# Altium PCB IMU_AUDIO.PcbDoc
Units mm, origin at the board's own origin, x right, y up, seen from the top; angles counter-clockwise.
Board outline 152.4 x 101.6 mm, 2 copper layers (Top Layer, Bottom Layer); 89 components, 57 nets, 364 pads, 97 vias.
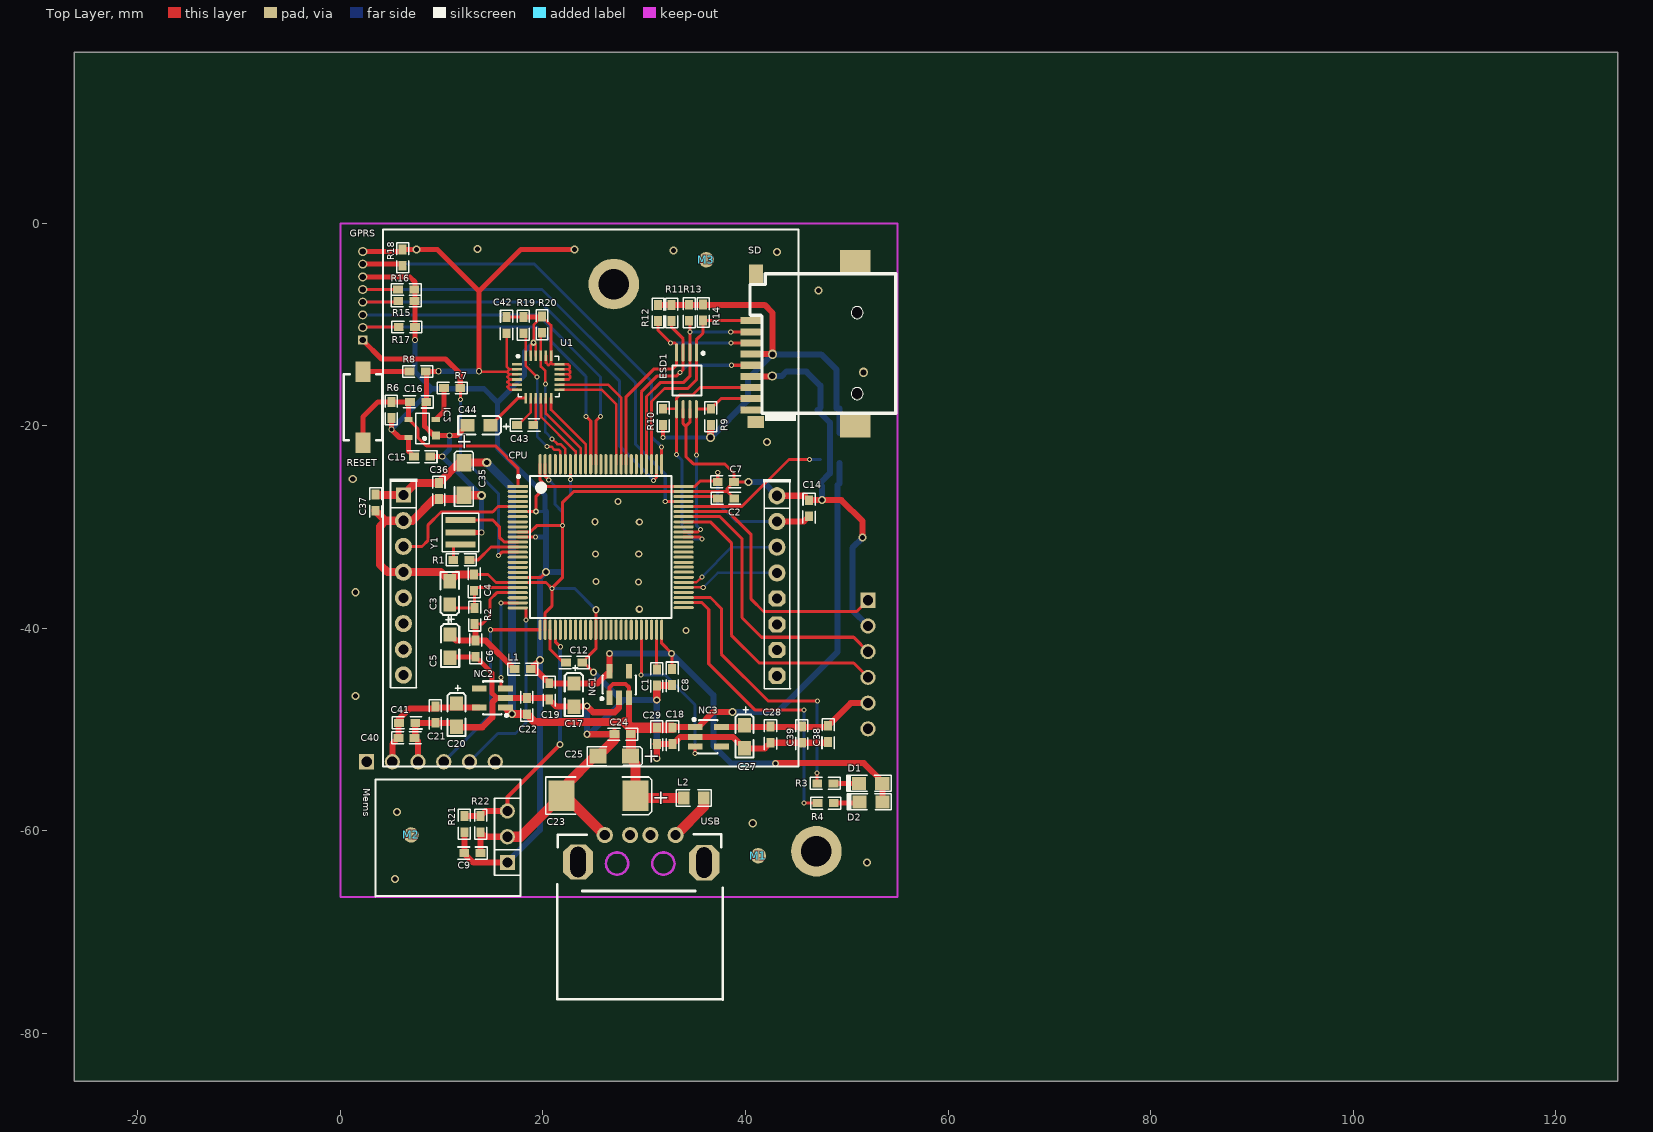
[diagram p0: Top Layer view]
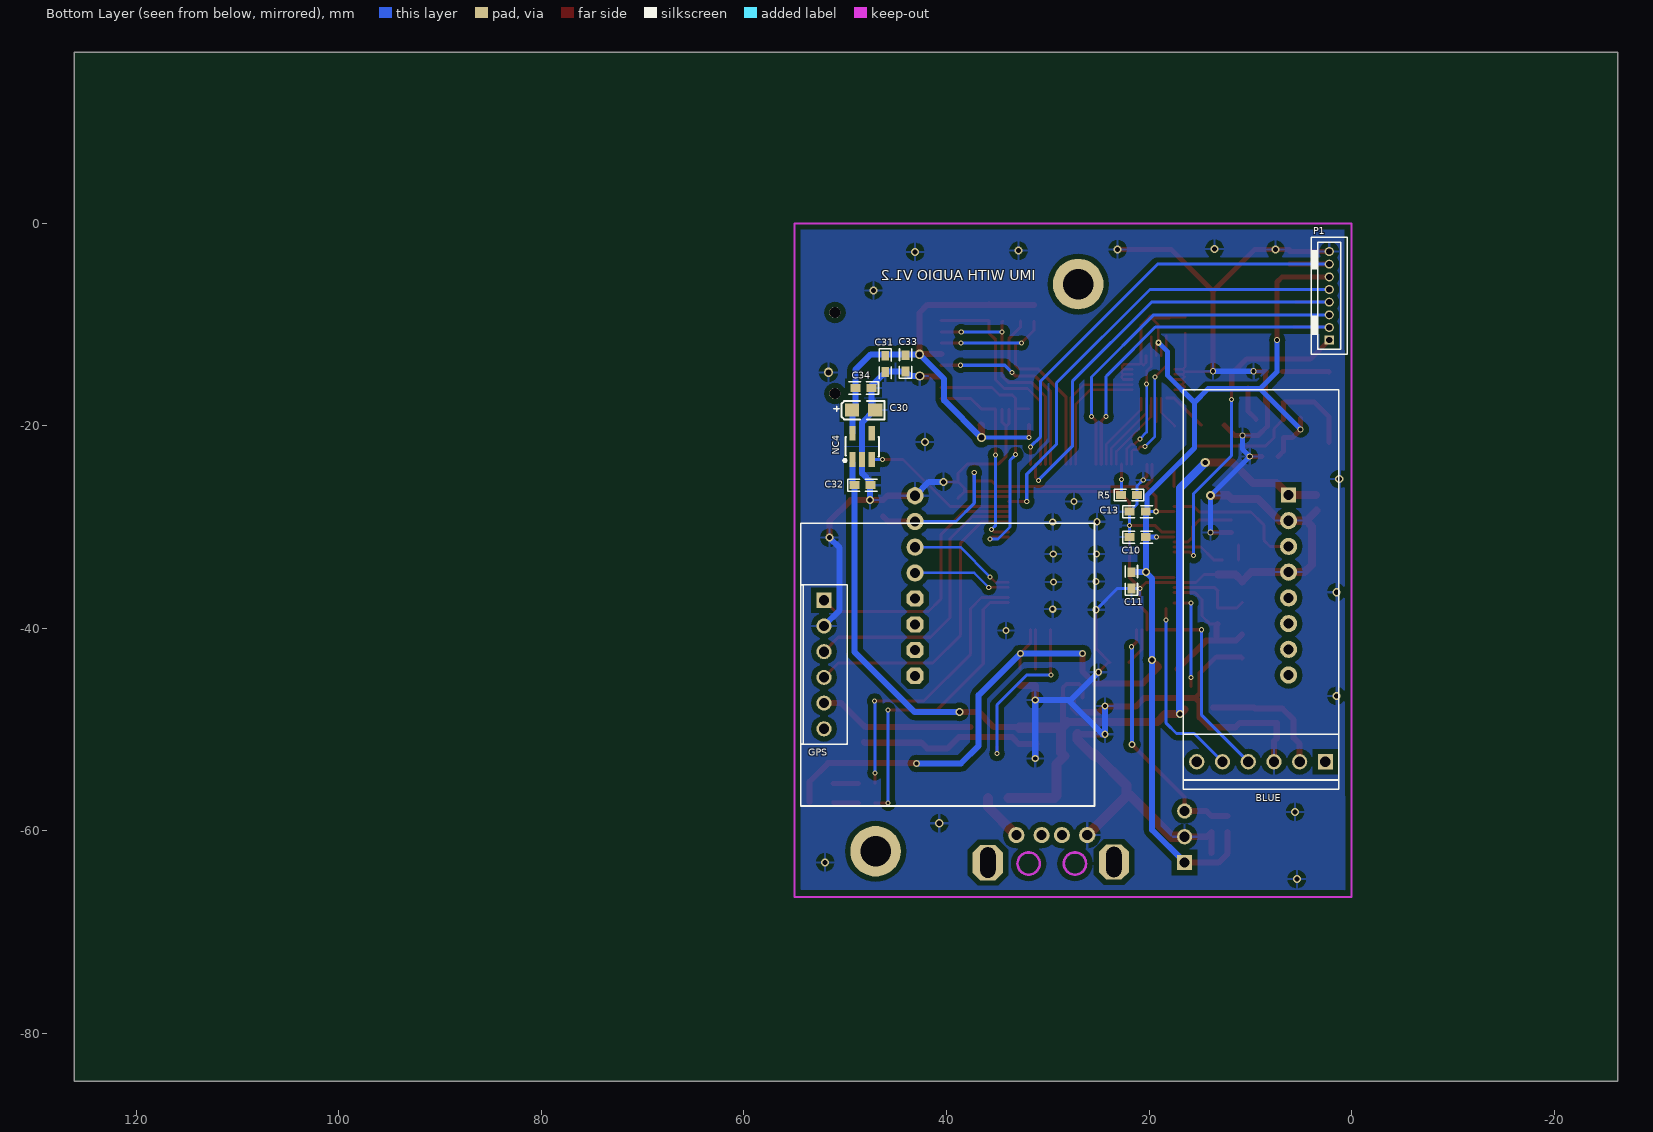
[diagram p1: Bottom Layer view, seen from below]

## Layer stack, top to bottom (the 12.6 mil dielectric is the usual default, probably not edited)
Top Layer: signal copper 0.0356
Dielectric: dielectric 0.32, FR-4, Dk 4.8
Bottom Layer: signal copper 0.0356

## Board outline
-26.273,-84.709 126.127,-84.709 126.127,16.891 -26.273,16.891

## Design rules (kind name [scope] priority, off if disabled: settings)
Clearance [All] p1: gap=0.2
PolygonConnect [All] p1: connectstyle=Relief reliefconductorwidth=0.254 reliefentries=4 polygonreliefangle="90 Angle"
RoutingVias [All] p1: holewidth=0.711 width=1.27 viastyle="Through Hole" minholewidth=0.711 minwidth=1.27 maxholewidth=0.711 maxwidth=1.27
SilkscreenOverComponentPads [All] p1: minsilkscreentomaskgap=0.254
SolderMaskExpansion [All] p1: expansion=0.102
Width [All] p1: maxlimit=2 minlimit=0.1 preferedwidth=0.3
27 further rules are at their usual default settings.

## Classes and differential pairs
component class CPU_STM32F4: C1 C2 C3 C4 C5 C6 C7 C8 C9 C10 C11 C12 C13 C14 C15 C16 CPU D1 D2 IC2 L1 M1 M2 M3 M4 M5 R1 R2 R3 R4 R5 R6 R7 R8 RESET Y1
component class IMU_module: BLUE C35 C36 C37 C38 C39 C40 C41 C42 C43 C44 GPRS GPS Mems R19 R20 R21 R22 U1
component class IMU_POW: C17 C18 C19 C20 C21 C22 C23 C24 C25 C27 C28 C29 C30 C31 C32 L2 NC1 NC2 NC3 NC4 USB
component class IMU_SD: C33 C34 ESD1 P1 R9 R10 R11 R12 R13 R14 R15 R16 R17 R18 SD

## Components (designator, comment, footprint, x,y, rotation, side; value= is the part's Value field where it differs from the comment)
BLUE "蓝牙模块" HC-06(35.7*15.2MM) 2.591,-53.162 r0 bottom locked (schematic designator P3)
C1 "1uF" 0603 31.242,-45.644 r90 top
C2 "1uF" 0603 38.887,-27.153 r180 top
C3 "1uF/10V" C-0805 10.795,-36.525 r90 top
C4 "100n" 0603 13.208,-34.671 r270 top
C5 "1uF/10V" C-0805 10.846,-41.707 r270 top
C6 "100n" 0603 13.36,-41.199 r270 top
C7 "100n" 0603 38.862,-25.527 r180 top
C8 "100n" 0603 32.766,-45.593 r90 top
C9 "100n" 0603 12.243,-62.179 r0 top
C10 "100n" 0603 20.32,-30.988 r0 bottom
C11 "100n" 0603 21.742,-34.442 r270 bottom
C12 "100n" 0603 22.276,-43.358 r0 top
C13 "100n" 0603 20.32,-28.473 r0 bottom
C14 "100n" 0603 46.279,-28.931 r90 top
C15 "100n" 0603 7.264,-23.038 r0 top
C16 "100n" 0603 6.883,-17.628 r0 top
C17 "4u7/6.3V" C-0805 23.063,-46.533 r270 top
C18 "100n" 0603 32.791,-51.41 r90 top
C19 "100n" 0603 20.625,-47.015 r90 top
C20 "4u7/6.3V" C-0805 11.481,-48.514 r270 top
C21 "100n" 0603 9.373,-49.301 r90 top
C22 "100n" 0603 18.415,-46.864 r270 top
C23 "470 u/10V" C-D(7343-31) 29.134,-56.515 r180 top
C24 "100n" 0603 27.076,-50.444 r0 top
C25 "4u7/10V" C-A(3216-18) 28.651,-52.603 r180 top
C27 "4u7/6.3V" C-0805 39.903,-50.648 r270 top
C28 "100n" 0603 42.469,-51.283 r90 top
C29 "100n" 0603 31.242,-51.41 r90 top
C30 "4u7/6.3V" C-0805 48.235,-18.44 r180 bottom
C31 "100n" 0603 46.05,-14.681 r90 bottom
C32 "100n" 0603 47.498,-25.857 r0 bottom
C33 "100n" 0603 44.044,-13.03 r270 bottom
C34 "100n" 0603 48.997,-16.256 r180 bottom
C35 "47uF/10V" C-A(3216-18) 12.192,-23.647 r270 top
C36 "100n" 0603 9.728,-27.229 r90 top
C37 "100n" 0603 3.48,-28.372 r90 top
C38 "100n" 0603 48.158,-51.206 r90 top
C39 "100n" 0603 45.568,-51.283 r90 top
C40 "100n" 0603 7.331,-50.8 r180 top
C41 "100n" 0603 7.391,-49.327 r180 top
C42 "100n" 0603 16.408,-10.846 r90 top
C43 "220n" 0603 19.05,-19.914 r180 top
C44 "4u7/6.3V" C-0805 13.741,-19.939 r180 top
CPU "STM32F40x-VG (LQFP100)" "LQFP100 (14*14)" 24.273,-30.683 r0 top locked (schematic designator IC1)
D1 "LED red" D0805 53.508,-55.296 r180 top
D2 "LED red" D0805 53.534,-57.125 r180 top
ESD1 "PESD5V0L6UAS" MSOP-8 35.154,-12.751 r270 top
GPRS "SIM800" SIM800 4.216,-53.619 r0 top locked (schematic designator GPRS1)
GPS "GPS" "GPS 28*28MM" 54.397,-57.404 r180 bottom locked (schematic designator P2)
IC2 "MAX6315US26D2-T" TO-253 8.661,-19.736 r180 bottom
L1 "22uH" 0603 18.796,-44.018 r180 top
L2 "22uH" 0805 35.89,-56.744 r180 top
M1 "CON-PAD" BAD_MARK 41.275,-62.433 r0 top
M2 "CON-PAD" BAD_MARK 6.985,-60.376 r0 top
M3 "CON-PAD" BAD_MARK 36.144,-3.581 r0 top
Mems "ADMP401" ADMP401 17.764,-66.421 r180 top locked (schematic designator Mems1)
NC1 "NCP603SN330T1G" TSSOP-5 27.178,-45.974 r90 top
NC2 "NCP603SN330T1G" TSSOP-5 15.443,-47.219 r180 top
NC3 "NCP603SN330T1G" TSSOP-5 35.89,-50.343 r0 top
NC4 "NCP603SN330T1G" TSSOP-5 48.692,-22.454 r90 bottom
P1 "CON-SIP8-2.0" PLUG1.27-8P 2.21,-11.532 r90 bottom
R1 "390" 0603 11.151,-33.223 r0 top
R2 "47" 0603 13.259,-39.573 r90 top
R3 "1K" 0603 48.682,-55.296 r180 top
R4 "1K" 0603 48.708,-57.252 r180 top
R5 "10K" 0603 21.184,-26.822 r0 bottom
R6 "47K" 0603 5.029,-17.628 r270 top
R7 "3.9K" 0603 10.236,-16.256 r0 top
R8 "10K" 0603 8.433,-14.63 r180 top
R9 "10K" 0603 36.576,-18.313 r270 top
R10 "10K" 0603 31.877,-18.313 r270 top
R11 "10K" 0603 32.715,-9.652 r90 top
R12 "10K" 0603 31.369,-9.652 r90 top
R13 "10K" 0603 34.442,-9.627 r90 top
R14 "10K" 0603 35.814,-9.601 r90 top
R15 "3.9K" 0603 5.715,-7.671 r0 top
R16 "3.9K" 0603 5.69,-6.532 r0 top
R17 "3.9K" 0603 5.766,-10.236 r0 top
R18 "3.9K" 0603 6.147,-2.591 r270 top
R19 "10K" 0603 18.059,-10.846 r90 top
R20 "10K" 0603 19.914,-10.795 r90 top
R21 "10K" 0603 12.243,-58.522 r270 top
R22 "10K" 0603 13.852,-60.122 r90 top
RESET "Manual Pushbutton" KEY-6*4 2.235,-14.656 r0 top (schematic designator S1)
SD "SD_CARD_SLOT" mini-SD 41.326,-11.252 r0 top locked (schematic designator J1)
U1 "LSM9DS0" QFN(4*4*0.9) 17.45,-13.919 r0 top
USB "车载转换头" USB-SMT 23.038,-63.119 r0 top (schematic designator J(USB)1)
Y1 "8Mhz" XT-3.2*1.5 11.862,-29.312 r270 top

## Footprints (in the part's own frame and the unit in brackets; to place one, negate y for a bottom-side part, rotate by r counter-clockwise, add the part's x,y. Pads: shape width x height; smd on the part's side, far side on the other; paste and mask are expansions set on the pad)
0603 [mil]
  rect 38x31 smd: 1(0,0) 2(63,0)
  silkscreen extent -26,-24 90,24
0805 [mil]
  rect 45x50 smd: 1(0,0) 2(78.74,0)
  silkscreen extent -29,-32 108,32
ADMP401 [mm] "MEMS 语音模块"
  rect 1.5x1.5 hole 1: 1(1.276,-3.315)
  round 1.5 hole 1: 2(1.276,-5.855) 3(1.276,-8.395)
  silkscreen extent 0,-11.52 14.32,0.02
BAD_MARK [mil] "MARK 点"
  round 60 smd mask+29.53: 0(-0.25,-0.63)
C-0805 [mm]
  rect 1.4x1.27 smd: 1(-1.096,-0.007) 2(1.19,-0.007)
  silkscreen extent -2.89,-0.91 2.1,0.92
C-A(3216-18) [mm]
  rect 1.7x1.47 smd: 1(0,0) 2(3.2,0)
  silkscreen extent -1.14,-0.92 4.28,0.94
C-D(7343-31) [mm]
  rect 2.54x3 smd: 1(0,0) 2(7.3,0)
  silkscreen extent -1.62,-1.85 8.87,1.86
D0805 [mm]
  rect 1.4x1.27 smd: A(0,0) K(2.286,0)
  silkscreen extent -0.87,-0.8 3.5,0.8
"GPS 28*28MM" [mm] "28*28MM  BS-280"
  rect 1.5x1.5 hole 1.016: 1(2.296,20.193)
  round 1.5 hole 1.016: 2(2.296,17.653) 3(2.296,15.113) 4(2.296,12.573) 5(2.296,10.033) 6(2.296,7.493)
  silkscreen extent 0,-0.13 29.01,27.81
HC-06(35.7*15.2MM) [mm] "蓝牙模块"
  rect 1.5x1.5 hole 1.016: 1(0,0)
  round 1.5 hole 1.016: 2(2.54,0) 3(5.08,0) 4(7.62,0) 5(10.16,0) 6(12.7,0)
  silkscreen extent -1.33,-36.72 14.03,2.7
KEY-6*4 [mm] "2PIN"
  rect 1.5x2 smd: 1(0,0) 2(0,-7)
  silkscreen extent -1.9,-6.75 1.9,-0.25
"LQFP100 (14*14)" [mm]
  rect 2x0.3 smd: 1(-6.751,4.716)
  oval 2x0.3 smd: 2(-6.751,4.216) 3(-6.751,3.716) 4(-6.751,3.216) 5(-6.751,2.716) 6(-6.751,2.216) 7(-6.751,1.716) 8(-6.751,1.216) 9(-6.751,0.716) 10(-6.751,0.216) 11(-6.751,-0.284) 12(-6.751,-0.784) 13(-6.751,-1.284) 14(-6.751,-1.784) 15(-6.751,-2.284) 16(-6.751,-2.784) 17(-6.751,-3.284) 18(-6.751,-3.784) 19(-6.751,-4.284) 20(-6.751,-4.784) 21(-6.751,-5.284) 22(-6.751,-5.784) 23(-6.751,-6.284) 24(-6.751,-6.784) 25(-6.751,-7.284) 51(9.629,-7.264) 52(9.629,-6.764) 53(9.629,-6.264) 54(9.629,-5.764) 55(9.629,-5.264) 56(9.629,-4.764) 57(9.629,-4.264) 58(9.629,-3.764) 59(9.629,-3.264) 60(9.609,-2.784) 61(9.609,-2.284) 62(9.609,-1.784) 63(9.609,-1.284) 64(9.609,-0.784) 65(9.609,-0.284) 66(9.609,0.216) 67(9.609,0.716) 68(9.609,1.216) 69(9.609,1.716) 70(9.609,2.216) 71(9.609,2.716) 72(9.609,3.216) 73(9.609,3.716) 74(9.609,4.216) 75(9.609,4.716)
  oval 0.3x2 smd: 26(-4.551,-9.444) 27(-4.051,-9.444) 28(-3.551,-9.444) 29(-3.051,-9.444) 30(-2.551,-9.444) 31(-2.051,-9.444) 32(-1.551,-9.444) 33(-1.051,-9.444) 34(-0.551,-9.444) 35(-0.051,-9.444) 36(0.449,-9.444) 37(0.949,-9.444) 38(1.449,-9.444) 39(1.949,-9.444) 40(2.449,-9.444) 41(2.949,-9.444) 42(3.449,-9.444) 43(3.949,-9.444) 44(4.449,-9.444) 45(4.949,-9.444) 46(5.449,-9.444) 47(5.949,-9.444) 48(6.449,-9.444) 49(6.949,-9.444) 50(7.449,-9.444) 76(7.449,6.896) 77(6.949,6.896) 78(6.449,6.896) 79(5.949,6.896) 80(5.449,6.896) 81(4.949,6.896) 82(4.449,6.896) 83(3.949,6.896) 84(3.449,6.896) 85(2.949,6.896) 86(2.449,6.896) 87(1.949,6.896) 88(1.449,6.896) 89(0.949,6.896) 90(0.449,6.896) 91(-0.051,6.896) 92(-0.551,6.896) 93(-1.051,6.896) 94(-1.551,6.896) 95(-2.051,6.896) 96(-2.551,6.896) 97(-3.051,6.896) 98(-3.551,6.896) 99(-4.051,6.896) 100(-4.551,6.896)
  silkscreen extent -6.8,-8.28 8.43,5.8
mini-SD [mm]
  rect 1.629x1.225 smd: 0(-0.301,-8.358)
  rect 1.4x1.93 smd: 0(-0.301,6.242)
  rect 3x2.2 smd: 0(9.5,-8.778) 0(9.5,7.52)
  rect 2.057x0.7 smd: 1(-0.801,1.642) 2(-0.801,0.542) 3(-0.801,-0.558) 4(-0.801,-1.658) 5(-0.801,-2.758) 6(-0.801,-3.858) 7(-0.801,-4.958) 8(-0.801,-6.058) 9(-0.801,-7.158)
  round 1.1 hole 1.1: ""(9.699,-5.558) ""(9.699,2.442)
  silkscreen extent -0.88,-8.26 13.5,6.29
MSOP-8 [mm]
  oval 1.8x0.3 smd: 1(0,0) 2(0,-0.65) 3(0,-1.3) 4(0,-1.95) 5(5.6,-1.95) 6(5.6,-1.3) 7(5.6,-0.65) 8(5.6,0)
  silkscreen extent -0.05,-2.34 4.24,0.79
PLUG1.27-8P [mm] "1.27mm  1*8p"
  rect 0.9x0.9 hole 0.6: 1(0,0)
  round 0.9 hole 0.6: 2(1.25,0) 3(2.5,0) 4(3.75,0) 5(5,0) 6(6.25,0) 7(7.5,0) 8(8.75,0)
  silkscreen extent -1.4,-1.78 10.16,1.78
QFN(4*4*0.9) [mm]
  rect 1x0.25 smd: 1(0,0) 2(0,-0.5) 3(0,-1) 4(0,-1.5) 5(0,-2) 6(0,-2.5) 13(4.2,-2.5) 14(4.2,-2) 15(4.2,-1.5) 16(4.2,-1) 17(4.2,-0.5) 18(4.2,0)
  rect 0.25x1 smd: 7(0.85,-3.347) 8(1.35,-3.347) 9(1.85,-3.347) 10(2.35,-3.347) 11(2.85,-3.347) 12(3.35,-3.347) 19(3.35,0.847) 20(2.85,0.847) 21(2.35,0.847) 22(1.85,0.847) 23(1.35,0.847) 24(0.85,0.847)
  silkscreen extent -0.01,-3.2 4.15,0.91
SIM800 [mm] "GPRS模块"
  rect 1.5x1.5 hole 1: 1(2.004,26.799)
  round 1.7 hole 1 unplated: 2(38.889,26.722) 3(2.004,24.259) 4(38.889,24.182) 5(2.004,21.719) 6(38.889,21.642) 7(2.004,19.179) 8(38.889,19.102) 9(2.004,16.639) 11(2.004,14.099) 13(2.004,11.559) 15(2.004,9.019)
  oct 1.7x1.6 hole 1 unplated: 10(38.889,16.562) 12(38.889,14.022) 14(38.889,11.482) 16(38.889,8.942)
  silkscreen extent 0,0 41,53
TO-253 [mm]
  rect 0.8x0.8 smd far side: 1(-0.781,-1.219)
  rect 0.8x0.5 smd far side: 2(-0.761,0.381) 3(1.919,0.381) 4(1.919,-1.419)
TSSOP-5 [mm]
  rect 1.45x0.6 smd: 1(-0.864,0.595) 2(-0.864,-0.355) 3(-0.864,-1.305) 4(1.736,-1.305) 5(1.736,0.595)
  silkscreen extent -1.09,-2 1.34,1.48
USB-SMT [mm]
  oct 3x3.5 hole 1.5 slot 3 at 90 deg: 0(0.43,0.058) 0(12.874,0)
  round 1.6 hole 1: 1(3.07,2.71) 2(5.57,2.71) 3(7.57,2.71) 4(10.07,2.71)
  Keep-Out Layer circle w0.254: c8.86,-0.1 r1.1
  Keep-Out Layer circle w0.254: c4.28,-0.1 r1.1
  silkscreen extent -1.63,-13.55 14.74,2.81
XT-3.2*1.5 [mm] "3.2*1.3*0.4mm"
  rect 0.6x3 smd: 1(0,0) 2(1.2,0) 3(2.4,0)
  silkscreen extent -0.7,-1.8 3.1,1.8

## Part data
BLUE: library part CON-SIP6-2.54, "单排针6PIN"
C1 C2 C4 C6 C7 C8 C9 C10 C11 C12 C13 C14 C15 C16 C18 C19 C21 C22 C24 C28 C29 C31 C32 C36 C37 C38 C39 C40 C41 C42 C43: library part Cap, "TANTAMOUNT? 595D Vishay Sprague,50V,22.5mOhm"
C3 C5 C17 C20 C25 C27 C30 C35 C44: library part C-A(3216-18)
C23: library part C-RB.1
C33 C34: library part Cap, "Capacitor"
CPU: library part STM32F40x-VG
D1 D2: library part diode-LED, "LED"
ESD1: library part PESD5V0L6U
GPRS: library part MHDR2X8, "Header, 8-Pin, Dual row"
GPS: library part CON6-2.54, "(栅)围栏式立(卧)6PIN"
IC2: library part "MAX 6468", "MAX 6468XS16D3 Reset and Supervisory Circuit"
L1: library part Inductor, "fcm1608-0603"
L2: library part INDUCTOR
Mems: library part MHDR1X3, "Header, 3-Pin"
NC1 NC2 NC3 NC4: library part NCP551
P1: "单排针8PIN"
R1 R2 R5 R19 R20 R21 R22: library part R-0603, "0603(SMD)"
R3 R4 R6 R7 R8 R9 R10 R11 R12 R13 R14: library part Res3, "Resistor"
R15 R16 R17 R18: library part R-0805, "0805(SMD)"
RESET: library part 微动开关
USB: library part CON-USB1, "USB"
Y1: library part CRYSTAL-X3, "3PIN"

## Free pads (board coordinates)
  round 5 hole 3: 0(27,-6) 0(47,-62)

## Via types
v1: diameter 0.5, hole 0.3, Top Layer to Bottom Layer, 42 vias
v2: diameter 0.8, hole 0.5, Top Layer to Bottom Layer, 21 vias
v3: diameter 0.7, hole 0.4, Top Layer to Bottom Layer, 19 vias
v4: diameter 0.6, hole 0.4, Top Layer to Bottom Layer, 7 vias
v5: diameter 0.9, hole 0.6, Top Layer to Bottom Layer, 4 vias
v6: diameter 0.6, hole 0.3, Top Layer to Bottom Layer, 2 vias
v7: diameter 0.9, hole 0.5, Top Layer to Bottom Layer, 2 vias

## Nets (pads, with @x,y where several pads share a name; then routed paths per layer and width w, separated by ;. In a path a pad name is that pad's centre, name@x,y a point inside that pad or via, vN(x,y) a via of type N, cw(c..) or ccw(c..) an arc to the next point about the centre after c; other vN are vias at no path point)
"BOOT0 (VPP)": CPU.94 R5.2 | length 3
  Top Layer w0.3: v1(22.722,-25.313) CPU.94
  Bottom Layer w0.3: R5.2@22.722,-26.761 v1(22.722,-25.313)
GND: BLUE.3 C1.1 C2.1 C3.2 C4.1 C5.2 C6.2 C7.1 C8.1 C9.2 C10.2 C11.2 C12.2 C13.2 C14.2 C15.2 C16.2 C17.2 C18.1 C19.1 C20.2 C21.1 C22.1 C23.2 C24.1 C25.2 C27.2 C28.1 C29.1 C30.2 C31.1 C32.1 C33.2 C34.2 C35.2 C36.1 C37.1 C38.1 C39.1 C40.1 C41.1 C42.1 C44.2 CPU.10 CPU.20 CPU.27 CPU.37 CPU.74 CPU.99 ESD1.6 ESD1.7 GPRS.2 GPRS.3 GPRS.7 GPS.2 IC2.1 Mems.2 NC1.2 NC2.2 NC3.2 NC4.2 P1.8 R5.1 R8.1 R18.1 R22.1 SD.6 U1.2 U1.3 U1.4 U1.5 U1.6 USB.1 Y1.2 | length 333.3
  Top Layer w0.254: C44.2 C44.2@12.723,-19.932 ; v4(13.69,-14.604) 13.741,-14.656 16.459,-14.656 ; C42.1 16.408,-14.132 16.696,-14.419 ; U1.6 16.765,-16.419 16.501,-16.154 16.736,-15.919 ; U1.5 16.736,-15.919 ; U1.4 16.733,-15.419 ; U1.3 16.723,-14.919 ; U1.2 16.696,-14.419 ; 16.459,-14.656 16.696,-14.419 ; 16.459,-14.656 16.723,-14.919 ; 16.723,-14.919 16.478,-15.164 16.733,-15.419 ; 16.733,-15.419 16.485,-15.668 16.736,-15.919
  Top Layer w0.3: C4.1 14.574,-34.671 15.37,-35.467 CPU.20 20.303,-35.467 v1(20.879,-36.043) ; CPU.10 18.758,-30.467 19.38,-29.845 v1(21.92,-29.845) ; CPU.27 20.222,-38.456 20.879,-37.799 v1(20.879,-36.043) ; CPU.99 20.222,-24.972 v1(20.574,-25.324) ; v3(24.994,-44.323) 24.028,-43.358 C12.2 25.222,-42.012 CPU.37 v3(25.222,-38.151) ; ESD1.6 33.854,-19.782 34.112,-20.041 ; ESD1.7 34.504,-19.649 34.112,-20.041 ; C2.1 38.202,-26.467 ; v2(40.31,-25.527) C7.1 ; v1(20.879,-36.043) 21.92,-35.001 v1(21.92,-29.845) ; v1(21.92,-29.845) 21.92,-27.584 23.037,-26.467 CPU.74 38.202,-26.467 ; 34.112,-20.041 34.112,-23.012 34.849,-23.749 37.922,-23.749 38.862,-24.689 C7.1 ; 38.202,-26.467 38.202,-26.187 C7.1
  Top Layer w0.5: P1.8 R18.1@6.147,-2.782 ; R18.1 v2(7.518,-2.591) 9.575,-2.591 13.69,-6.706 ; C15.2 v4@10.033,-23.038 ; v4@9.652,-14.63 R8.1 8.484,-14.681 C16.2 8.306,-17.805 8.306,-19.974 8.325,-19.993 8.325,-20.034 9.245,-20.954 IC2.1 v4(10.795,-20.954) 11.529,-20.954 C44.2 ; C5.2 10.937,-42.799 C6.2 14.986,-44.425 14.986,-46.406 15.444,-46.864 ; Y1.2 v4@13.919,-30.512 ; v4(13.69,-14.604) 13.69,-6.706 ; v2(23.114,-2.565) 17.83,-2.565 13.69,-6.706
  Top Layer w0.6: BLUE.3 7.671,-51.14 7.391,-50.86 C41.1 11.046,-49.327 11.474,-49.755 14.025,-49.755 15.011,-48.768 15.011,-47.301 15.449,-46.864 NC2.2 C22.1 20.473,-46.864 C19.1 21.332,-47.723 C17.2 v3@24.359,-47.723 ; C9.2 13.852,-62.17 R22.1 14.297,-60.566 Mems.2 ; v3(24.359,-50.444) C24.1 ; v3@24.406,-47.723 24.954,-48.271 27.091,-48.271 27.533,-47.829 NC1.2 ; C29.1@31.14,-51.41 C18.1 32.851,-51.41 33.563,-50.698 NC3.2 38.757,-50.698 C27.2 41.914,-51.838 C28.1 C39.1 48.082,-51.283 C38.1 ; v3(31.242,-52.857) C29.1 ; SD.6 42.624,-15.11 v5(42.647,-15.088) ; GPRS.2 45.845,-26.897 C14.2 v2(47.574,-27.33) 49.479,-27.33 51.562,-29.413 v2(51.562,-31.039)
  Top Layer w0.7: v3(31.242,-47.066) C1.1 32.715,-45.644 C8.1
  Top Layer w0.8: C37.1 4.469,-29.361 ; C4.1 11.466,-34.671 C3.2 9.907,-34.441 GPRS.7 4.646,-34.441 3.912,-33.706 3.912,-29.918 4.469,-29.361 ; v7@13.894,-26.847 C35.2 11.811,-27.229 C36.1 9.246,-27.229 7.114,-29.361 GPRS.3 4.469,-29.361
  Top Layer w1: Mems.2 17.783,-60.566 C23.2 ; C25.2@25.299,-52.451 C25.2@25.146,-52.603 ; USB.1 22.214,-56.515 22.214,-55.536 C25.2@25.146,-52.603 ; C24.1 27.076,-50.978 C25.2 C25.2@25.146,-52.603
  Bottom Layer w0.3: v1(20.574,-25.324) 21.184,-25.933 R5.1 21.184,-27.737 C13.2 v1(21.92,-29.845) C10.2 ; v1(20.879,-36.043) C11.2 23.114,-36.043 v3(25.222,-38.151)
  Bottom Layer w0.5: v4(9.677,-14.604) v4(13.69,-14.604) ; v4(10.795,-20.954) 10.795,-22.275 v4(10.058,-23.012) v7(13.919,-26.873) v4(13.919,-30.531)
  Bottom Layer w0.6: v3(24.359,-47.676) v3(24.359,-50.444) 24.587,-50.444 27.965,-47.066 ; v3(24.994,-44.323) 27.737,-47.066 27.965,-47.066 ; v3(31.242,-52.857) v3(31.242,-47.066) 27.965,-47.066 ; v2(40.31,-25.527) 41.735,-25.527 GPRS.2 ; v5(42.647,-15.088) 43.586,-15.088 C33.2 45.999,-14.63 C31.1 47.396,-16.027 C34.2 C30.2@47.396,-18.172 ; C30.2@47.121,-18.447 48.337,-19.663 NC4.2 48.337,-24.684 C32.1@47.407,-25.614 ; v2(47.574,-27.33) C32.1@47.574,-25.933 ; v2(51.562,-31.039) 50.549,-32.051 50.549,-38.199 GPS.2
  other v2: 5.41,-64.745 51.994,-63.094 40.716,-59.233 5.588,-58.115 1.499,-46.66 1.499,-36.424 1.219,-25.248 42.139,-21.59 47.219,-6.629 43.104,-2.819 32.893,-2.692 13.538,-2.515
  other v3: 34.138,-40.208 29.515,-38.1 29.439,-35.433 25.222,-35.357 29.464,-32.664 25.197,-32.639 29.515,-29.489 25.146,-29.464 27.432,-27.457
  other v5: 51.664,-14.707
NetC16_1: C16.1 CPU.1 IC2.3 R6.1 RESET.2 | length 27
  Top Layer w0.3: 5.436,-17.628 C16.1 C16.1@6.742,-17.769 ; IC2.3 7.671,-20.283 7.671,-21.158 8.484,-21.971 10.82,-21.971 ; 10.287,-21.971 10.82,-21.971 ; CPU.1 17.522,-24.177 15.316,-21.971 10.82,-21.971
  Top Layer w0.5: RESET.2 2.235,-19.101 3.708,-17.628 R6.1 ; 5.436,-17.628 R6.1 ; IC2.3 6.742,-17.769 6.601,-17.628 R6.1
NetC18_2: C18.2 C22.2 C23.1 C24.2 C25.1 C29.2 C32.2 C35.1 C36.2 C37.2 GPRS.1 L2.2 NC1.1 NC1.3 NC2.1 NC3.1 NC4.1 | length 112
  Top Layer w0.4: NC1.1 26.583,-45.832 26.924,-45.491 28.169,-45.491 28.483,-45.806 NC1.3
  Top Layer w0.6: 28.483,-49.225 NC1.3 ; C18.2@33.082,-49.748 NC3.1 NC3.1@35.317,-49.748 ; 36.17,-48.895 NC3.1@35.317,-49.748 ; v2(38.71,-48.235) 36.83,-48.235 NC3.1@35.317,-49.748
  Top Layer w0.8: C37.2@3.529,-26.821 GPRS.1 7.413,-25.629 C36.2 11.735,-23.622 v7(14.453,-23.622) ; NC2.1@16.49,-48 v2(16.953,-48.464) C22.2 19.176,-49.225 28.092,-49.225
  Top Layer w1: 28.092,-49.225 28.677,-49.809 31.14,-49.809 C18.2 ; C25.1@28.346,-52.603 29.134,-53.391 C23.1 29.362,-56.744 L2.2 ; C25.1@28.702,-52.248 28.702,-51.003 28.702,-50.444 28.702,-49.835
  Bottom Layer w0.6: v2@38.71,-48.26 41.605,-48.26 43.155,-48.26 49.098,-42.316 C32.2 ; C32.2@49.287,-25.669 NC4.1@49.287,-23.673
  Bottom Layer w0.8: v7@14.478,-23.673 16.953,-26.148 v2(16.953,-48.464)
NetC20_1: BLUE.2 C20.1 C21.2 C40.2 C41.2 NC2.5 | length 12.9
  Top Layer w0.6: BLUE.2 5.131,-51.4 C40.2 5.731,-49.006 6.833,-47.904 9.576,-47.904 9.667,-47.814 NC2.5
NetC27_1: C27.1 C28.2 C38.2 C39.2 GPS.5 NC3.5 | length 15.5
  Top Layer w0.6: NC3.5 45.568,-49.748 48.017,-49.748 C38.2 50.394,-47.371 GPS.5
NetC30_1: C30.1 C31.2 C33.1 C34.1 NC4.5 R9.2 R10.2 R11.2 R12.2 R13.2 R14.2 SD.4 | length 48.9
  Top Layer w0.4: v1(31.877,-21.158) R10.2
  Top Layer w0.6: R12.2 R11.2 34.976,-8.052 41.885,-8.052 42.672,-8.839 v5(42.672,-12.929) 42.654,-12.91 SD.4 ; R14.2@35.763,-8.052 R14.2
  Top Layer w0.7: v5(36.551,-21.158) 36.551,-19.939 R9.2
  Bottom Layer w0.4: v1(31.877,-21.158) v5(36.551,-21.158)
  Bottom Layer w0.6: v5(36.551,-21.158) 40.234,-17.474 40.234,-15.366 v5(42.672,-12.929) C33.1@43.79,-12.929 ; C33.1@44.018,-12.929 46.05,-12.929 47.473,-12.929 48.997,-14.453 C34.1 C30.1@48.997,-18.277 ; NC4.5 C30.1@49.287,-18.277
NetC43_1: C43.1 U1.9 | length 2.3
  Top Layer w0.254: C43.1@19.3,-19.588 U1.9
NetC43_2: C43.2 U1.8 | length 3.3
  Top Layer w0.254: C43.2@17.45,-20.015 18.8,-18.665 U1.8
NetC44_1: C44.1 U1.7 | length 4.5
  Top Layer w0.3: C44.1 17.503,-17.266 U1.7@18.269,-17.266
NetD1_K: D1.K R3.1 | length 2.5
  Top Layer w0.5: R3.1 D1.K
NetD2_K: D2.K R4.1 | length 2.6
  Top Layer w0.3: D2.K@51.121,-57.252 D2.K
  Top Layer w0.5: R4.1 D2.K@51.121,-57.252
NetESD1_1: CPU.78 ESD1.1 R14.1 SD.1 | length 22.4
  Top Layer w0.3: CPU.78 30.722,-17.589 32.004,-16.307 33.757,-16.307 34.315,-16.307 35.154,-15.469 ESD1.1 35.154,-11.506 35.814,-10.846 R14.1 40.516,-9.601 SD.1
NetESD1_2: CPU.79 ESD1.2 R13.1 SD.2 | length 23.3
  Top Layer w0.3: CPU.79 30.222,-17.098 31.623,-15.697 33.909,-15.697 34.504,-15.103 ESD1.2 v1(34.504,-10.719) 34.504,-9.688 R13.1 ; v1(38.549,-10.71) SD.2
  Bottom Layer w0.3: v1(34.504,-10.719) 34.512,-10.71 v1(38.549,-10.71)
NetESD1_3: CPU.80 ESD1.3 R11.1 SD.5 | length 24.7
  Top Layer w0.3: CPU.80 29.722,-16.633 31.293,-15.062 33.223,-15.062 33.854,-14.432 ESD1.3 33.854,-11.4 32.715,-10.262 R11.1 ; v1(38.618,-14.01) SD.5
  Bottom Layer w0.3: v1(33.553,-14.707) 34.25,-14.01 v1(38.618,-14.01)
NetESD1_4: CPU.83 ESD1.4 R12.1 SD.3 | length 26.2
  Top Layer w0.3: CPU.83 28.222,-17.117 30.937,-14.402 32.791,-14.402 33.204,-13.99 ESD1.4 33.204,-11.969 33.045,-11.81 v1(32.614,-11.81) 31.369,-10.565 R12.1 ; v1(38.583,-11.81) SD.3
  Bottom Layer w0.3: v1(32.614,-11.81) v1(38.583,-11.81)
NetESD1_5: CPU.65 ESD1.5 R10.1 SD.7 | length 26.4
  Top Layer w0.254: R10.1 ESD1.5@33.166,-18.313
  Top Layer w0.3: v1@33.204,-22.835 ESD1.5 33.204,-17.241 33.503,-16.942 34.773,-16.942 35.504,-16.21 39.141,-16.21 SD.7 ; CPU.65 35.514,-30.967 v1(35.712,-31.166)
  Bottom Layer w0.3: v1(33.172,-22.835) 33.74,-23.402 33.74,-29.981 34.925,-31.166 v1(35.712,-31.166)
NetESD1_8: CPU.66 ESD1.8 R9.1 SD.8 | length 19.6
  Top Layer w0.3: CPU.66 35.319,-30.467 v1(35.56,-30.226) ; v1(35.154,-22.885) ESD1.8 36.539,-18.351 R9.1 37.579,-17.31 SD.8
  Bottom Layer w0.3: v1(35.154,-22.885) 35.154,-29.82 v1(35.56,-30.226)
NetGPRS_5: CPU.5 GPRS.5 | length 13.8
  Top Layer w0.3: GPRS.5 8.054,-31.901 8.674,-31.28 8.674,-29.769 9.944,-28.499 15.039,-28.499 15.57,-27.967 CPU.5
NetGPRS_6: CPU.56 GPRS.6 | length 10.6
  Top Layer w0.254: CPU.56 35.139,-35.447 v1(35.687,-34.9)
  Bottom Layer w0.254: v1(35.687,-34.9) 38.61,-31.977 GPRS.6
NetGPRS_8: CPU.55 GPRS.8 | length 9.8
  Top Layer w0.254: CPU.55 v1(35.833,-35.947)
  Bottom Layer w0.254: v1(35.833,-35.947) 37.263,-34.517 GPRS.8
NetIC1_24: CPU.24 NC2.3 | length 9.9
  Top Layer w0.3: NC2.3@15.875,-45.745 v1(15.875,-44.831) ; v1@15.875,-37.465 v1(15.877,-37.467) CPU.24
  Bottom Layer w0.3: v1(15.875,-44.831) v1(15.877,-37.467)
NetIC1_25: BLUE.5 CPU.25 | length 18.5
  Top Layer w0.3: v1(18.313,-39.167) CPU.25@18.313,-38.024
  Bottom Layer w0.3: BLUE.5 15.545,-50.368 17.297,-50.368 18.313,-49.352 v1(18.313,-39.167)
NetIC1_26: BLUE.4 CPU.26 | length 19.9
  Top Layer w0.3: v1(14.813,-40.127) CPU.26
  Bottom Layer w0.3: BLUE.4 14.813,-48.56 v1(14.813,-40.127)
NetIC1_29: CPU.29 Mems.3 R21.1 R22.2 | length 24.7
  Top Layer w0.3: CPU.29 21.222,-41.313 v1(21.717,-41.808)
  Top Layer w0.4: Mems.3 16.488,-56.664 v3(21.692,-51.46)
  Top Layer w0.6: R21.1 R22.2 14.348,-58.026 Mems.3
  Bottom Layer w0.4: v3(21.692,-51.46) v1@21.692,-41.834
NetIC1_46: CPU.46 NC3.3 | length 16.6
  Top Layer w0.3: v1@29.722,-44.602 CPU.46 ; v1(35.026,-52.349) NC3.3
  Bottom Layer w0.3: v1(29.693,-44.602) 32.08,-44.602 35.026,-47.548 v1(35.026,-52.349) v1@34.975,-52.4
NetIC1_52: CPU.52 R4.2 | length 30
  Top Layer w0.3: CPU.52 35.695,-37.447 36.373,-38.125 36.373,-43.485 40.919,-48.031 v1(45.796,-48.031) ; v1(45.771,-57.252) R4.2
  Bottom Layer w0.3: v1(45.771,-57.252) v1@45.771,-48.031
NetIC1_53: CPU.53 R3.2 | length 28.3
  Top Layer w0.3: CPU.53 36.541,-36.947 37.617,-38.024 37.617,-42.545 42.24,-47.168 v1(47.092,-47.168) ; v1(47.066,-54.254) 47.082,-54.27 R3.2@47.082,-55.17 ; R3.2 R3.2@47.082,-55.17 ; R3.2@47.092,-55.169 47.084,-55.169 R3.2@47.082,-55.17
  Bottom Layer w0.3: v1@47.082,-47.168 47.082,-54.321 v1@47.092,-54.331
NetIC1_68: CPU.68 GPS.4 | length 29.9
  Top Layer w0.3: CPU.68 36.528,-29.467 38.608,-31.547 38.608,-40.665 41.351,-43.409 50.679,-43.409 GPS.4
NetIC1_69: CPU.69 GPS.3 | length 28.3
  Top Layer w0.3: CPU.69 37.476,-28.967 39.649,-31.14 39.649,-38.938 41.58,-40.869 50.679,-40.869 GPS.3
NetIC1_70: CPU.70 GPS.1 | length 26.5
  Top Layer w0.3: CPU.70 38.297,-28.467 40.564,-30.734 40.564,-37.109 41.783,-38.329 50.984,-38.329 GPS.1
NetIC1_71: CPU.71 NC4.3 | length 15.4
  Top Layer w0.3: CPU.71 39.648,-27.967 44.297,-23.318 v1(46.304,-23.318)
  Bottom Layer w0.3: v1(46.304,-23.318) NC4.3
NetIC1_72: CPU.72 P1.5 R16.1 | length 49.3
  Top Layer w0.3: P1.5 R16.1@5.973,-6.532 ; v1@32.055,-27.467 CPU.72
  Bottom Layer w0.3: P1.5 19.917,-6.532 29.134,-15.748 29.134,-21.819 32.08,-24.765 v1(32.08,-27.457)
NetIC1_76: CPU.76 P1.7 R18.2 | length 45.9
  Top Layer w0.3: CPU.76 v1@31.722,-22.075
  Top Layer w0.5: P1.7 R18.2@6.147,-4.032
  Bottom Layer w0.3: P1.7 19.17,-4.032 30.709,-15.57 30.709,-21.057 v1(31.725,-22.073)
NetIC1_77: CPU.77 P1.4 R15.1 | length 44.9
  Top Layer w0.3: P1.4 R15.1@5.604,-7.782 ; v1(30.937,-25.375) 31.222,-25.09 CPU.77
  Bottom Layer w0.3: P1.4 19.77,-7.782 27.584,-15.596 27.584,-22.022 v1(30.937,-25.375)
NetIC1_84: CPU.84 U1.14 | length 13.2
  Top Layer w0.254: U1.14 25.952,-15.919 26.435,-15.919 27.722,-17.206 CPU.84
NetIC1_85: CPU.85 U1.13 | length 12.1
  Top Layer w0.254: U1.13 25.792,-16.419 27.222,-17.849 CPU.85
NetIC1_89: CPU.89 P1.3 | length 34.7
  Top Layer w0.3: CPU.89 25.222,-19.507 v1(25.679,-19.05)
  Bottom Layer w0.3: P1.3 19.547,-9.032 25.679,-15.164 v1@25.679,-18.898
NetIC1_90: CPU.90 P1.2 R17.1 | length 38.1
  Top Layer w0.3: P1.2 2.255,-10.236 R17.1 ; v1(24.257,-19.05) 24.722,-19.515 CPU.90
  Bottom Layer w0.3: P1.2 2.255,-10.236 14.605,-10.236 ; 13.792,-10.236 14.605,-10.236 ; 24.13,-14.986 23.597,-14.453 ; v1(24.257,-19.05) 24.257,-15.113 23.597,-14.453 ; 14.605,-10.236 19.38,-10.236 23.597,-14.453
NetIC1_91: CPU.91 U1.12 | length 7.9
  Top Layer w0.254: U1.12 20.8,-18.387 24.222,-21.809 CPU.91
NetIC1_92: CPU.92 U1.11 | length 7.9
  Top Layer w0.254: U1.11 20.3,-18.776 23.722,-22.198 CPU.92
NetIC1_93: CPU.93 U1.10 | length 9.1
  Top Layer w0.254: U1.10 19.8,-19.089 19.808,-19.097 ; 19.808,-17.938 19.808,-19.097 ; CPU.93 23.222,-22.511 19.808,-19.097
NetIC1_95: CPU.95 R20.1 U1.21 | length 13.8
  Top Layer w0.254: R20.1@19.787,-11.201 19.8,-11.215 U1.21 19.8,-14.148 20.244,-14.592 v1(20.244,-15.85) ; v1(20.904,-21.285) 21.418,-21.799 21.748,-21.799 22.222,-22.273 CPU.95
  Bottom Layer w0.254: v1(20.244,-15.85) 20.244,-20.625 v1(20.904,-21.285)
NetIC1_96: CPU.96 R19.1 U1.24 | length 14.6
  Top Layer w0.254: R19.1@18.3,-11.086 U1.24 18.3,-14.058 v1(19.431,-15.189) ; v1(20.422,-22.047) 20.828,-22.047 21.117,-22.336 21.549,-22.336 21.722,-22.509 CPU.96
  Bottom Layer w0.254: v1(19.431,-15.189) 19.431,-21.057 v1(20.422,-22.047)
NetIC2_2: IC2.2 R7.1 | length 3.4
  Top Layer w0.5: IC2.2 10.236,-18.54 R7.1
NetJ(USB)1_4: L2.1 USB.4 | length 4.8
  Top Layer w1: USB.4 35.89,-57.627 L2.1
NetR1_1: R1.1 Y1.3 | length 1.4
  Top Layer w0.3: R1.1 Y1.3@11.151,-31.774
NetR8_2: R8.2 RESET.1 | length 4.6
  Top Layer w0.5: RESET.1 2.261,-14.63 R8.2
NRST: CPU.14 P1.1 R7.2 | length 32.6
  Top Layer w0.3: v1(11.862,-17.399) R7.2@11.862,-16.281 ; v1(15.596,-32.817) 15.945,-32.467 CPU.14
  Top Layer w0.5: P1.1 4.064,-13.386 10.389,-13.386 11.836,-14.834 R7.2
  Bottom Layer w0.3: v1(11.862,-17.399) 11.862,-22.936 15.596,-26.67 v1(15.596,-32.817)
"PH0-OSC_IN (OSC_IN)": CPU.12 Y1.1 | length 7.2
  Top Layer w0.3: Y1.1 14.021,-29.312 15.062,-29.312 15.697,-29.946 15.697,-30.988 16.176,-31.467 CPU.12
"PH1-OSC_OUT (OSC_OUT)": CPU.13 R1.2 | length 5.3
  Top Layer w0.3: R1.2 13.614,-33.223 14.87,-31.967 CPU.13
VBAT: C7.2 C8.2 C9.1 C10.1 C11.1 C13.1 C14.1 C15.1 C17.1 C19.2 C42.2 CPU.6 CPU.11 CPU.19 CPU.50 CPU.75 CPU.100 D1.A D2.A GPRS.4 IC2.4 L1.1 Mems.1 NC1.5 P1.6 R6.2 R15.2 R16.2 R17.2 R19.2 R20.2 R21.2 U1.15 U1.16 U1.17 U1.18 U1.19 U1.20 U1.22 U1.23 | length 222.7
  Top Layer w0.254: C42.2 R19.2 ; U1.23 18.8,-12.061 v6@19.063,-11.798 ; v6@19.075,-11.786 19.075,-10.033 19.863,-9.246 R20.2 20.8,-10.081 U1.19 20.8,-13.789 ; U1.22 19.3,-12.01 ; U1.20@20.308,-13.072 20.308,-13.76 20.568,-14.021 20.8,-13.789 ; U1.15 22.53,-15.419 ; U1.16 22.504,-14.919 ; U1.17 22.504,-14.419 ; 22.53,-15.411 22.708,-15.233 22.708,-15.122 22.504,-14.919 ; 20.8,-13.789 20.93,-13.919 U1.18 22.479,-13.919 22.657,-14.097 22.657,-14.267 22.504,-14.419 ; 22.504,-14.919 22.708,-14.716 22.708,-14.622 22.504,-14.419
  Top Layer w0.3: CPU.19 19.795,-34.967 v2(20.32,-34.442) ; CPU.11 v1(19.274,-30.967) ; CPU.6 v6(19.298,-28.467) ; v6@19.304,-28.467 19.304,-26.992 20.328,-25.967 ; CPU.100 19.722,-25.361 20.328,-25.967 ; CPU.50 31.722,-41.476 v3(32.715,-42.469) 32.766,-42.52 C8.2 ; C7.2@37.162,-25.527 C7.2 v1(37.262,-24.613) ; C7.2@37.162,-25.427 35.56,-25.427 35.02,-25.967 CPU.75 20.328,-25.967
  Top Layer w0.5: P1.6 6.856,-5.282 7.366,-5.791 R17.2 v4(7.366,-11.532) ; R6.2 v4(5.029,-20.345) 5.838,-21.154 IC2.4 6.742,-22.515 C15.1 ; R19.2 R20.2@19.863,-9.246
  Top Layer w0.6: R21.2 C9.1 12.243,-62.239 13.131,-63.127 16.468,-63.127 Mems.1 ; v2(19.71,-43.104) 19.012,-43.802 C19.2 ; C19.2@20.625,-45.437 C17.1 25.384,-45.437 NC1.5 v3@26.583,-42.469 ; v3@42.951,-53.289 51.682,-53.289 53.534,-55.141 D2.A ; GPRS.4 45.772,-29.437 C14.1
  Bottom Layer w0.3: v6(19.298,-28.467) 20.314,-28.467 C13.1 ; v1(37.262,-24.613) 37.262,-27.635 39.064,-29.437 GPRS.4
  Bottom Layer w0.5: 7.366,-18.009 v4(5.029,-20.345) 9.042,-16.332 ; v4(7.366,-11.532) 7.366,-14.656 9.042,-16.332 ; 18.161,-24.816 18.669,-25.324 ; v6(19.05,-11.786) 18.161,-12.675 18.161,-15.037 15.519,-17.678 ; v1(19.274,-30.967) C10.1@20.299,-30.967 ; C13.1@20.314,-28.467 20.197,-28.35 C13.1@20.197,-28.325 ; C13.1 20.32,-28.448 C13.1@20.197,-28.325 ; 9.042,-16.332 14.173,-16.332 15.519,-17.678 ; 15.519,-17.678 15.519,-22.174 18.669,-25.324 ; 18.669,-25.324 20.197,-26.852 C13.1@20.197,-28.325
  Bottom Layer w0.6: Mems.1 19.71,-59.884 v2(19.71,-43.104) 19.71,-35.052 v2(20.32,-34.442) ; C13.1 C10.1 v2(20.32,-34.442) ; C11.1 v2(20.32,-34.442) ; v3@26.583,-42.469 v3(32.715,-42.469) v3@32.73,-42.483 ; v3@32.73,-42.469 v3@32.73,-42.483 ; v3(42.951,-53.336) 38.579,-53.336 36.83,-51.587 36.83,-46.584 v3@32.73,-42.483
  other v3: 26.568,-42.469
VCAP_1: C1.2 CPU.49 | length 3.9
  Top Layer w0.3: C1.2@31.222,-44.024 CPU.49
VCAP_2: C2.2 CPU.73 | length 3.2
  Top Layer w0.3: CPU.73 C2.2@37.102,-26.967
VDD4: C12.1 CPU.28 | length 3.8
  Top Layer w0.3: CPU.28 20.722,-42.083 C12.1@21.996,-43.358
VDDA: C5.1 C6.1 CPU.22 L1.2 R2.1 | length 15.9
  Top Layer w0.3: R2.1 13.97,-39.573 14.77,-38.773 14.77,-37.148 15.45,-36.467 CPU.22
  Top Layer w0.6: C5.1 11.427,-41.199 C6.1 ; R2.1 13.36,-39.675 C6.1 ; L1.2 14.376,-41.199 C6.1
VREF+: C3.1 C4.2 CPU.21 R2.2 | length 8.8
  Top Layer w0.3: C3.1@10.802,-37.443 11.332,-37.973 R2.2 13.259,-36.373 C4.2@13.208,-36.322 ; C4.2 13.512,-35.967 15.164,-35.967 CPU.21
pads on no net: BLUE.1 BLUE.6 CPU.2 CPU.3 CPU.4 CPU.7 CPU.8 CPU.9 CPU.15 CPU.16 CPU.17 CPU.18 CPU.23 CPU.30 CPU.31 CPU.32 CPU.33 CPU.34 CPU.35 CPU.36 CPU.38 CPU.39 CPU.40 CPU.41 CPU.42 CPU.43 CPU.44 CPU.45 CPU.47 CPU.48 CPU.51 CPU.54 CPU.57 CPU.58 CPU.59 CPU.60 CPU.61 CPU.62 CPU.63 CPU.64 CPU.67 CPU.81 CPU.82 CPU.86 CPU.87 CPU.88 CPU.97 CPU.98 GPRS.9 GPRS.10 GPRS.11 GPRS.12 GPRS.13 GPRS.14 GPRS.15 GPRS.16 GPS.6 M1.0 M2.0 M3.0 NC1.4 NC2.4 NC3.4 NC4.4 SD. SD.0 SD.9 U1.1 USB.0 USB.2 USB.3

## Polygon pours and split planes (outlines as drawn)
GND on Bottom Layer "Bottom Layer-No Net" (solid, remove dead copper, pour order 1000): 0.711,-0.406 54.305,-0.406 54.407,-0.508 54.407,-65.71 54.331,-65.786 0.813,-65.786 0.635,-65.964

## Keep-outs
Keep-Out Layer:
  lines w0.2: 0,-66.5 55,-66.5 55,0 0,0 0,-66.5

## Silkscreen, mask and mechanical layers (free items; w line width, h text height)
Bottom Overlay:
  text "IMU WITH AUDIO V1.2" at 31.191,-5.613 h1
